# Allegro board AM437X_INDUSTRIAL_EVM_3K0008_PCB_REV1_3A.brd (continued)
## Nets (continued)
Pads without a net: J1 18; J3 9; J4 2; J5 14 16; J6 7; J7 6; J9 7; J18 4; NOREF 1; NOREF#4 1; NOREF#5 1; NOREF#6 1; NOREF#7 1; NOREF#8 1; NOREF#10 1; NOREF#11 1; NOREF#15 1; NOREF#16 1; NOREF#17 1; NOREF#18 1; NOREF#20 1; NOREF#21 1; NOREF#22 1; NOREF#24 1; NOREF#25 1; NOREF#26 1; NOREF#27 1; NOREF#28 1; NOREF#29 1; NOREF#30 1; R143 1; U4 4 6 8 10 12 16 17 19 21 27; U7 22; U8 1; U11 A5 A6 A7 AA7 AA9 AA10 AA19 AB6 AB7 AB9 AB10 AB19 AC5 AC6 AC7 AC9 AC10 AC12 AC24 AD1 AD2 AD7 AD10 AD11 AD22 AE7 AE8 AE9 AE10 AE11 AE12 B5 B6 B7 B8 C8 F24 F25 G21 G24 H19 M4 N6 T2 T25 U2 U22 U23 U24 U25 V24 V25 W10 W22 W24 W25 Y6 Y7 Y10; U12 22; U13 22 24 27 29 33 34 40 41 43 44 45 46 48 52 53 54 55 57 58; U20 J1 J9 L1 L9 M7; U21 J1 J9 L1 L9 M7; U23 21; U26 11 13 19 20; U27 4 9; U28 1; U33 2 4; U36 1; U37 45; U42 1; U46 4 5 6 11 12 13 14; U47 2; U48 1; U51 1; U54 1; U58 7 8 9 10; U59 2 5; Y1 2 4; Y3 2 3

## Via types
v1: diameter 0.457, hole 0.254, TOP to BOTTOM, 1263 vias
v2: diameter 0.508, hole 0.254, TOP to BOTTOM, 19 vias
v3: diameter 0.61, hole 0.305, TOP to BOTTOM, 1023 vias
v4: diameter 1.016, hole 0.508, TOP to BOTTOM, 123 vias

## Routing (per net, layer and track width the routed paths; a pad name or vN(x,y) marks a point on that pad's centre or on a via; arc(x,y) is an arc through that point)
AGND: length 2
  TOP w0.203: J5.1 125.2,105.56 125.41,105.78 125.41,106.11
  TOP w0.381: C15.2 125.41,106.11
AGNDFRAME_PRUETH0: length 9.3
  L5_PWR w0.508: J6.SHLD1 10.96,100.03 ; J6.SHLD1 8.96,100.03 ; J6.SHLD1 10.96,98.02 ; J6.SHLD2 10.96,82.27 ; J6.SHLD2 8.96,82.27 ; J6.SHLD2 10.96,84.28
  BOTTOM w0.508: C137.2 10.54,102.11 v3(10.53,102.1)
AGNDFRAME_PRUETH1: length 9.4
  L5_PWR w0.508: J9.SHLD1 10.96,74.02 ; J9.SHLD1 10.96,76.03 ; J9.SHLD1 8.96,76.03 ; 8.96,58.27 J9.SHLD2 ; J9.SHLD2 10.96,58.27 ; J9.SHLD2 10.96,60.28
  BOTTOM w0.508: C188.2 v3(10.41,77.98)
DGND: length 668.8
  TOP w0.13: U20.E2 v1(70.87,36.82)
  TOP w0.203: U11.A1 72.22,59.35 v1(71.82,59.75) ; U20.E8 75.64,36.8 v1(74.76,36.8) ; U21.G8 94.73,35.65 95.12,36.04 95.12,36.77 v1(95.16,36.81) ; J5.5 123.6,105.51 v3(123,106.11) 122.8,105.91 J5.7
  TOP w0.254: U13.13 121.75,63.21 v3(121.73,63.2) ; U20.E1 69.98,37.22 69.95,37.18 69.56,37.18 v1(69.47,37.09) ; v3(124.33,58.94) 124.06,59.21 U13.5 ; v1(69.55,38.04) 69.79,38.04 69.82,38.02 U20.D1 ; 92.33,17.27 92.58,17.02 92.58,16.97 92.89,16.66 93.19,16.66 93.35,16.5 U25.4 ; v1(96.7,31.88) 96.43,31.62 U21.M9 ; v1(87.99,58.94) 88.29,59.23 U11.AE1 ; U21.P1 88.95,30.02 v1(88.53,29.59) ; U21.E8 v1(95.13,37.62) ; U21.B9 95.65,39.73 v1(96.08,39.73) ; U13.10 122.06,61.71 v3(121.54,62.23) ; U20.G8 75.75,35.31 75.75,35.23 v1(75.74,35.22) ; U20.M1 69.98,31.62 69.85,31.74 v1(69.83,31.74) ; U21.D8 v1(94.33,37.62) ; v1(69.96,35.53) 70.04,35.62 U20.G1 ; U21.B3 v1(91.13,40.02) ; v1(77.36,31.69) 77.18,31.69 77.11,31.62 U20.M9 ; v1(86.24,73.25) 85.84,73.65 U11.AA23 ; U21.T1 89.13,28.13 88.75,27.75 v1(88.53,27.75) ; v1(95.12,34.37) 95.1,34.34 95.05,34.34 U21.J8 ; U11.W23 83.98,73.65 83.94,73.68 v1(83.89,73.68) ; v1(88.7,74.68) 88.43,74.95 U11.AE25 ; U20.T1 70.37,28.51 69.91,28.51 69.88,28.53 v1(69.72,28.53) ; v3(117.34,68.05) 117.2,68.05 116.98,67.82 U13.25 ; U20.F9 77.18,36.42 v1(77.35,36.25) ; U13.47 v3(112.72,57.71) ; v1(77.31,39.16) 77.3,39.16 76.86,39.6 U20.B9 ; U21.A9 95.62,40.32 v1(96.08,40.32) ; v3(60.58,13.97) 61.1,13.45 U26.6 ; v1(95.98,35.94) 95.98,35.91 95.69,35.62 U21.G9 ; U20.A9 76.86,40.84 76.94,40.92 v1(76.94,40.94) ; U20.B1 69.92,40.15 69.92,40.34 v1(69.9,40.36) ; U13.51 v3(114.48,53.72) ; v1(77.45,28.47) 77.4,28.42 U20.T9 ; U21.T9 95.53,27.97 v1(95.45,27.89) ; v1(72.1,74.56) 72.1,74.57 72.48,74.95 U11.A25 ; U13.1 v3(124.21,57.21) ; U21.B1 88.97,39.78 88.6,39.78 v1(88.57,39.8) ; U20.G9 77.1,35.62 77.11,35.61 77.32,35.61 77.78,35.15 77.78,35.09 78.08,34.8 v1(78.08,34.78) ; v1(71.7,34.42) 71.66,34.42 U20.J2 ; v1(96,36.61) 95.97,36.61 95.78,36.42 U21.F9 ; U13.11 v3(124.12,62.21) ; U26.12 62.84,9.57 v3(62.85,9.56) ; U20.P9 77.04,30.02 77.14,30.12 77.21,30.12 v1(77.32,30.22) ; U21.P9 95.63,30.12 v1(96.42,30.12) ; v1(88.62,37.25) 88.66,37.22 U21.E1 U21.E2 ; U21.J2 89.53,34.42 89.53,34.36 89.55,34.34 v1(89.54,34.34) ; v3(71.75,101.66) 71.34,102.08 U4.28 ; U20.B3 72.48,40.03 v1(72.48,40.02) ; U20.J8 75.64,33.6 v1(75.59,33.6) ; U13.35 110.53,63.71 v3(110.11,64.14) ; v1(88.62,35.59) 88.65,35.62 U21.G1 ; U21.M1 88.51,31.62 v1(88.27,31.37) ; U21.D1 v1(88.73,38.42) ; U20.P1 69.33,30.02 69.27,30.09 v1(69.23,30.09) ; U20.D8 v1(76.46,37.62)
  TOP w0.305: v3(42.93,36.07) 43.39,35.6 U23.20 ; U13.15 v3(124.28,64.21) ; U23.28 v3(38.19,35.81) ; v3(93.85,14.22) U25.8 ; U27.5 v3(47.37,3.17)
  TOP w0.381: v3(122.82,84.45) 122.81,84.47 U8.3 ; U6.11 v3(109.94,99.35) ; U6.2 v3(115.8,97.03) ; U9.10 v3(64.26,85.22) ; U6.13 v3(109.29,90.68) ; U6.12 v3(109.29,97.03)
  TOP w0.457: v3(28.83,35.69) 28.58,35.94 U18.2 ; U24.2 v3(61.09,28.07) ; U19.2 v3(61.09,37.34)
  TOP w0.508: C18.2 v3(93.6,102.56) ; C9.2 v3(83.91,110.3) ; v3(108.08,47.5) 109.09,47.5 109.73,46.86 U16.7 ; C33.2 v3(21.59,89.67) ; v3(84.96,101.85) 84.58,102.23 U5.7 ; v3(33.91,96.52) R44.1 R46.1 ; v3(49.02,23.88) R213.1 C100.2 ; v3(14.3,110.06) 14.22,110.13 R7.1 ; v3(39.5,98.3) R32.2 ; SW1.3 v3(134.62,59.4) SW1.4 ; C116.2 v3(59.69,2.79) ; R181.1 109.09,44.12 v3(109.04,44.17) 108.84,44.37 C78.2 ; C29.2 v3(86.74,91.44) ; C90.2 v3(30.23,31.5) ; C11.2 v3(62.61,110.1) ; 101.73,53.09 101.73,51.94 v3(102.49,51.94) ; SW2.2 v3(133.13,33.69) ; R191.1 v3(57.02,38.61) ; U22.2 50.29,30.51 v3(50.52,30.28) ; C73.2 v3(124.08,53.22) 124.2,53.34 R160.1 ; U5.10 v3(84.58,97.28) ; R94.1 v3(124.19,80.39) ; Q3.S 18.92,110.66 v3(18.92,112.39) ; R108.1 33.91,70.35 v3(34.68,70.35) ; C84.2 R185.1 v3(30.61,41.91) ; v3(76.73,97.03) C23.2 v3(75.56,95.63) ; R34.1 v3(73.53,96.01) ; v3(102.92,34.85) 102.62,34.54 R198.1 ; R212.1 v3(58.93,25.1) ; C85.2 v3(58.93,39.37) ; R33.1 v3(68.71,96.65) ; J7.12 v3(128.4,80.77) ; U16.5 v3(113.16,49.4) ; U5.9 v3(83.31,97.28) ; C6.2 v3(76.29,110.3) ; C10.2 v3(88.56,110.3) ; C91.2 v3(53.34,32.26) ; v3(102.51,58.72) 101.9,58.72 101.73,58.55 ; v3(89.43,12.42) 89.59,12.57 C112.2 ; C3.2 v3(68.67,110.3) ; v3(98.12,19.3) 97.52,19.3 C105.2 97.03,18.8 97.54,18.29 v3(98.12,18.29) ; C34.2 v1(61.65,86.87) ; v3(34.68,92.17) 34.65,92.2 R55.1 ; v3(97.92,16.89) 97.92,16 C109.2 ; C72.2 v3(13.47,54.23) ; v3(67.08,41.16) C80.2 v3(64.64,41.16) ; C24.2 v3(74.55,94.36) ; C19.2 v3(94.74,102.56) ; C61.2 v3(127.26,62.81) ; v3(36.83,93.98) C26.2 ; R202.1 v3(64.01,30.48) ; 101.73,54.74 v3(102.49,54.74) ; R192.1 v3(25.27,39.12) ; R175.1 v3(34.42,51.55) ; C30.2 v3(89.28,91.44) ; v3(102.87,11.68) C113.2 v3(101.58,10.43) ; R166.1 v3(18.15,51.82) ; v3(60.71,4.19) C115.2 59.65,5.12 v3(59.44,5.33) ; C46.2 v3(112.39,77.36) ; C41.2 v3(118.11,84.89) ; C68.2 v3(104.77,58.17) ; v3(36.96,98.81) C22.2 36.59,97.65 v3(35.69,98.55) ; C87.2 v3(47.62,35.69) ; C114.2 v3(64.01,7.62) ; v3(62.36,30.35) 61.98,30.73 C92.2 ; R81.1 v3(92.71,84.84) ; R55.1 R51.1 ; R55.1 R57.1 ; C16.2 80.77,106.93 81.14,107.3 v3(81.15,107.3) ; 31.12,85.72 30.35,85.72 v3(29.69,85.06) ; U14.7 v3(22.1,54.34) ; v3(48.39,98.17) 48.39,99.08 C21.2 48.01,99.44 47.62,99.82 v3(47.62,100.71) ; v3(94.61,13.72) 94.74,13.59 C111.2 ; C75.2 v3(45.47,53.84) ; U5.16 v3(92.2,97.41) ; v3(122.43,113.59) 123.05,113.59 Q1.S ; J7.20 v3(128.4,85.85) ; C20.2 v3(117.22,101.09) ; v3(110.24,40) 110.24,40.64 C82.2 ; U15.7 v3(44.28,53.09) ; v3(25.91,112.39) 25.91,110.71 Q5.S ; C14.2 v3(121.09,107.88) ; R9.1 6.65,110.87 v3(6.39,111.14) ; C104.2 v3(89.94,18.8) ; Q4.S 22.48,110.66 v3(22.48,112.39) ; R122.1 33.91,69.21 v3(34.68,69.21) ; C108.2 v3(89.4,15.75) ; v3(26.42,39.12) C86.2 ; v3(55.55,91.69) 55.17,91.31 C28.2 v3(54.34,90.04) ; C107.2 v3(96.53,17.27) ; R112.1 v3(112.4,70.87) ; SW2.1 v3(135.11,33.69) ; C64.2 v3(28.56,60.45) ; R169.1 v3(116.08,50.94) ; C76.2 111.64,51.82 v3(111.63,51.82) ; C44.2 v3(124.33,81.53) ; R19.2 v3(64.52,106.55) ; R18.1 v3(49.92,106.81) ; C101.2 v3(61.98,21.08) ; C8.2 v3(81.37,110.3) ; v3(121.28,117.47) 121.79,117.47 R1.1 ; R130.1 R127.1 33.91,68.07 v3(34.68,68.07) ; R566.2 70.23,82.75 69.55,82.07 v3(69.49,82.07) ; C93.2 v3(59.69,29.34) ; v3(30.48,72.64) 31.67,72.64 C49.2 32.08,72.64 v3(33.27,72.64) ; v3(128.85,106.11) R17.1 v3(128.85,108.14) ; C110.2 v3(18.8,14.35) ; R182.1 v3(121.91,43.05) ; C25.2 v3(119.51,93.6) ; U3.7 v3(60.53,109.09) ; C4.2 v3(71.21,110.3) ; R93.2 v1(111.38,81.43) ; C103.2 v3(100.18,21.08) ; U10.7 v3(113.58,78.11) ; v3(35.54,80.26) C43.2 v3(35.54,82.73) ; C7.2 v3(78.83,110.3) ; C89.2 v3(48.51,36.07) ; Q2.S 127.83,114.55 v3(128.02,114.55) ; C17.2 50.04,105.66 v3(49.91,105.79) ; v3(82.68,102.49) 83.31,103.12 U5.8 ; v3(28.58,41.91) 28.58,41.15 C83.2 ; R53.1 v3(50.29,92.02) ; v3(51.05,94.61) 50.93,94.61 50.29,95.25 R45.1 ; C63.2 v3(39.5,61.09) ; R197.2 v3(50.42,36.07) ; J7.16 v3(128.4,83.31) ; J7.8 v3(128.4,78.23) ; R176.1 v3(46.48,49.66) ; v3(81.41,20.59) C102.2 v3(82.68,19.43) ; C62.2 v3(102.49,61.82) ; C60.2 103.76,65.41 v3(104.01,65.41) ; v3(11,110.01) 11.3,110.31 R11.1 ; C13.2 v3(118.81,107.88) ; C5.2 v3(73.75,110.3) ; C77.2 v3(34.42,48.91) ; C58.2 v3(21.59,64.4) ; C65.2 v3(31.12,59.69) ; C79.2 v3(122.05,44.2) ; C69.2 v3(13.47,56.52) ; U17.7 v3(111.25,40.77) ; R156.1 v3(13.47,55.37) ; 27.81,85.72 v3(28.56,85.72)
  L2_GND w0.508: 136.61,71.08 TP9.1 ; TP9.1 136.61,72.69 ; TP9.1 138.22,72.69 ; TP9.1 138.22,71.08 ; 104.57,117.49 J1.30 ; J1.30 104.57,116.06 ; J1.30 106,117.49 ; J1.30 106,116.06 ; 28.75,118.3 J4.12 ; J4.12 30.19,118.3 ; J4.12 30.19,116.87 ; J4.12 28.75,116.87 ; 135.19,24.72 J13.2 ; J13.2 136.81,24.72 ; J13.2 135.19,26.33 ; J13.2 136.81,26.33 ; J1.29 106,114.95 ; J1.29 104.57,113.52 ; J1.29 104.57,114.95 ; J1.29 106,113.52 ; 106.63,4.56 J16.22 ; J16.22 108.06,4.56 ; J16.22 106.63,3.13 ; J16.22 108.06,3.13 ; J1.17 90.76,113.52 ; J1.17 89.33,113.52 ; J1.17 89.33,114.95 ; J1.17 90.76,114.95 ; 63.08,3.73 TP16.1 ; TP16.1 63.08,2.12 ; TP16.1 64.69,3.73 ; TP16.1 64.69,2.12 ; J8.2 26.33,75.61 ; J8.2 24.72,75.61 ; J8.2 26.33,74 ; J8.2 24.72,74 ; 127.04,26.18 J12.2 ; J12.2 130,26.18 ; J12.2 127.04,29.14 ; J12.2 130,29.14 ; 68.63,6.56 J16.59 ; J16.59 70.06,5.13 ; J16.59 68.63,5.13 ; 14.48,1.91 J15.6 ; J15.6 16,1.91 ; J15.6 14.48,3.43 ; J15.6 16,3.43 ; 88.63,3.13 J16.40 ; J16.40 90.06,3.13 ; J16.40 90.06,4.56 ; J16.40 88.63,4.56 ; J3.10 15.54,108.51 ; J3.10 13.92,108.51 ; J3.10 13.92,106.88 ; J6.8 16.51,87.42 ; J6.8 16.51,85.99 ; J6.8 15.08,87.42 ; J6.8 15.08,85.99 ; 68.63,3.13 J16.60 ; J16.60 68.63,4.56 ; J16.60 70.06,4.56 ; J16.60 70.06,3.13 ; 42.2,116.27 J4.13 ; J4.13 43.64,114.84 ; J4.13 43.64,116.27 ; TP11.1 3.47,51.9 ; TP11.1 1.86,51.9 ; TP11.1 1.86,53.51 ; TP11.1 3.47,53.51 ; 130.29,21.38 J12.3 ; J12.3 133.25,24.34 ; J12.3 133.25,21.38 ; J12.3 130.29,24.34 ; TP1.1 58.34,118.15 ; TP1.1 56.73,116.54 ; TP1.1 56.73,118.15 ; TP1.1 58.34,116.54 ; 88.63,6.56 J16.39 ; J16.39 88.63,5.13 ; J16.39 90.06,5.13 ; J16.39 90.06,6.56 ; J4.1 42.63,104.84 ; J4.1 41.19,104.84 ; J4.1 41.19,103.41 ; J4.1 42.63,103.41 ; J9.8 16.51,61.99 ; J9.8 16.51,63.42 ; J9.8 15.08,61.99 ; J9.8 15.08,63.42
  L3_SIG1 w0.508: 15.08,85.99 J6.8 15.08,87.42
  L4_SIG2 w0.508: J6.8 16.51,85.99 ; J6.8 16.51,87.42 ; J6.8 15.08,85.99
  BOTTOM w0.203: U40.C1 v3(115.45,85.85) ; J19.13 55.33,1.78 ; v3(64.93,108.08) 65.31,107.7 U29.C1 ; U52.C1 v3(42.41,45.72) ; U49.5 131.1,49.57 v1(130.81,49.28) ; U41.5 128.43,83.35 v3(128.4,83.31) ; U53.C1 v3(113.16,48.13) ; J19.14 41.07,1.65
  BOTTOM w0.254: 100.46,92.58 100.81,92.94 U35.C4 ; U35.C1 104.62,92.94 104.9,93.22 v1(104.9,93.47) ; 102.57,94.71 102.33,94.47 102.33,94.07 U35.A2 ; U35.C3 U35.C4 ; U35.C4 U35.D4 ; v3(47.62,96.01) 47.07,95.46 U37.13 ; U37.29 43.93,90.44 v3(43.18,91.19)
  BOTTOM w0.305: U31.2 v3(134.37,102.23) ; U59.4 v3(54.6,19.17) ; U47.4 131.45,64 v3(130.94,64.52) ; U38.8 131.07,90.69 v3(131.44,91.06) ; U38.3 v3(134.33,90.93) ; U45.8 v3(124.47,68.07) ; U45.9 v3(124.47,71)
  BOTTOM w0.381: U38.9 131.07,94.1 v3(131.44,93.73) ; J19.6 v3(40.37,3.36) ; U50.3 124.47,50.68 v3(124.84,51.05) ; C301.2 v1(95.12,34.37) ; C193.2 85.58,73.91 v1(86.24,73.25) ; v1(88.57,39.8) 88.24,39.8 88.06,39.62 C283.2 ; U42.3 31,82.68 v3(31.31,82.99) ; U34.2 125.98,92.08 v3(125.73,91.82) ; J18.5 135.07,61.69 v3(134.54,61.17) ; v1(69.83,31.74) 69.67,31.74 69.54,31.88 C315.2 ; v3(14.1,74.74) U44.3 ; U33.10 v3(22.1,99.68) ; C294.2 89.32,37.25 v1(88.62,37.25) ; v1(69.47,37.09) 69.21,36.83 C297.2 ; C195.2 83.54,73.68 v1(83.89,73.68) ; v1(69.72,28.53) 69.71,28.53 69.5,28.32 C324.2 ; U58.11 37.34,28.82 v3(36.96,29.21) ; U36.3 v3(76.2,92.31) ; v3(135.64,93.6) 134.98,94.26 U38.15 ; U48.3 108.09,57.67 v3(108.58,58.17) ; U58.13 v3(37.99,20.31) ; U51.3 127.65,50.84 v3(127.54,50.95) ; C290.2 94.23,37.71 v1(94.33,37.62) ; U43.3 21.29,79.12 v3(20.57,79.12) ; U58.12 v3(37.99,26.42) ; v1(69.55,38.04) 69.48,38.04 69.41,37.97 C289.2 ; C285.2 77.01,39.45 77.3,39.16 v1(77.31,39.16) ; v3(135.76,45.97) 135.14,45.35 U54.3 ; v1(71.7,34.42) 71.66,34.46 71.66,35.08 C302.2 ; C187.2 v3(28.7,77.48) ; C328.2 89.22,27.75 v1(88.53,27.75) ; v3(125.73,96.65) 125.98,96.39 U34.5 ; C197.2 78.96,73.32 78.94,73.33 78.94,75.61 78.4,76.16 v3(78.4,76.2) ; U38.14 v3(134.33,93.89) ; U39.10 v3(55.75,92.71) ; v1(96.42,30.12) 96.69,29.84 C318.2 ; U33.5 v3(25.65,99.68)
  BOTTOM w0.508: R549.1 97.92,15.75 v3(97.92,16.89) ; C227.2 v3(117.79,64.27) ; v1(95.98,35.94) C296.2 ; v3(111.55,54.09) 111.57,54.11 C258.2 v3(110.61,55.07) ; C314.2 88.77,31.88 v1(88.27,31.37) 88.11,31.22 88.01,31.22 87.91,31.12 C316.2 ; Q8.S v3(6.39,111.14) ; R335.1 R334.1 R333.1 R332.1 R331.1 R330.1 R329.1 R328.1 v3(67.82,96.33) ; v3(57.75,9.65) R557.1 R556.1 ; v3(121.73,63.2) 121.78,63.25 R460.2 ; U32.3 v3(84.58,97.28) ; C186.2 128.52,78.36 v3(128.4,78.23) ; C190.2 v3(133.73,76.96) ; J19.12 v3(41.26,9.47) ; C149.2 v3(51.05,94.61) ; C142.2 v3(46.35,99.69) ; U32.2 v3(85.85,97.28) ; C295.2 74.88,36.88 74.79,36.8 v1(74.76,36.8) ; C139.2 v3(29.59,101.6) ; v1(76.46,37.62) 76.18,37.62 75.69,38.1 C288.2 ; v3(25.53,59.56) 25.15,59.94 R464.1 ; U46.10 46.32,68.45 v3(45.71,67.85) ; C344.2 v3(63.37,18.8) ; R315.1 R314.1 v3(67.69,100.97) ; R554.1 v3(26.38,12.42) ; v3(84.45,16.78) C342.2 v3(87,16.78) ; C170.2 133.48,86.23 v3(133.6,86.36) ; U56.3 v3(53.09,40.17) ; v1(96.7,31.88) 96.54,31.88 96.42,32 C312.2 ; v3(129.97,101.03) C136.2 v3(129.97,103.57) ; v3(56.93,13.97) 57.06,13.84 R550.1 57.78,12.86 R551.1 ; C226.2 v3(133.92,67.06) ; U55.5 v3(22.73,47.62) ; v3(25.91,112.39) 25.91,111.89 R274.1 ; C242.2 65.79,62.36 v3(65.91,62.23) ; C235.2 v3(128.91,62.86) ; R319.1 R318.1 v3(62.1,100.97) ; C250.1 v3(120.02,57.03) ; R452.1 34.78,65.63 v3(34.8,65.65) ; v3(61.85,39.5) C286.2 ; U57.5 v3(3.37,25.65) ; C147.2 21.54,96.27 22.1,95.71 22.12,95.71 v3(22.15,95.68) ; C177.2 76.07,82.43 v3(76.33,82.17) ; C208.2 v3(22.23,68.96) ; C225.2 v3(129.92,65.66) ; C274.1 v3(123.95,44.32) ; R301.1 v3(113.66,106.55) ; v3(22.23,85.29) C167.2 v3(21.03,86.5) ; C222.2 v3(21.46,66.04) ; v1(78.08,34.78) 78.16,34.78 78.95,35.56 79.12,35.56 ; R276.1 22.48,111.76 v3(22.48,112.39) ; C215.2 21.97,67.95 v3(22.23,68.2) ; J19.11 v3(55.76,10.96) ; v1(75.74,35.22) 76.07,35.55 C299.2 ; C178.2 v3(22.11,83.82) ; Q7.S v3(11,110.01) ; v1(69.96,35.53) 69.72,35.3 C304.2 ; C130.1 v3(18.92,105.03) ; C346.2 v3(61.09,18.8) ; 29.46,22.73 v3(28.7,22.73) ; v3(39.62,81.67) R398.1 R397.1 ; C137.1 v3(12.32,103) ; v3(21.85,30.1) R513.2 v3(20.84,29.09) ; C345.2 v3(62.23,18.8) ; C245.1 v3(117.61,62.83) ; v3(104.39,54.99) 104.65,55.24 R476.1 ; C334.2 60.83,24 v3(60.45,23.62) ; v3(22.1,60.13) C244.2 v3(20.9,61.23) ; C309.2 R509.1 v3(62.99,31.5) ; C143.2 v3(44.83,99.69) ; v3(52.96,33.15) 52.45,32.64 C91.2 ; v3(133.73,84.33) C174.2 ; v3(62.84,68.84) 62.97,68.71 C212.2 ; C335.2 v3(104.76,25.65) ; C335.2 v3(104.76,23.11) ; C335.2 v3(105.89,24.38) ; v1(96.08,40.32) 96.4,40.64 C282.2 ; C255.2 129.41,57.66 v3(129.92,58.17) ; C127.2 v3(88.9,105.92) ; v3(26.54,90.26) 26.32,90.04 C163.2 C164.2 ; v3(125.98,90.68) C156.2 ; C262.2 v3(138.4,53.59) ; v3(98.6,37.67) 98.3,37.97 C291.2 ; v3(47.88,28.83) 48.39,29.34 C325.2 ; v3(98.55,56.9) C257.2 97.39,57.49 97.93,58.03 v3(98.55,58.03) ; v1(84.48,32.49) 84.48,32.48 84.84,32.13 C311.2 ; v1(80.14,84.84) 79.88,84.58 C176.2 ; C263.2 v3(106.81,51.82) ; v3(64.9,100.97) R316.1 R317.1 ; C191.2 63.4,75.79 v3(62.67,75.79) ; C330.2 v3(71.45,27.17) ; v3(114.95,64.41) C228.2 v3(116.14,63.3) ; 133.73,69.47 133.73,68.32 v3(133.64,68.23) ; 133.73,69.47 v3(132.08,69.47) ; 133.73,69.47 v3(133.73,70.87) ; C326.2 45.85,29.72 v3(45.21,30.35) ; v1(91.13,40.02) 91.13,40.71 C278.2 ; C293.2 57.15,36.7 v3(57.02,36.58) ; C169.2 v3(128.4,85.85) ; C251.1 v3(117.65,57.19) ; C183.2 56.19,79.38 55.83,79.73 v3(55.83,80.14) ; C350.2 v3(30.91,13.1) ; U32.4 v3(83.31,97.28) ; C129.1 v3(23.49,105.03) ; v3(122.18,103.01) 122.36,103.18 R304.1 ; v3(59.31,100.97) R320.1 R321.1 ; C125.2 v3(112.14,108.08) ; v1(95.45,27.89) 95.5,27.84 C329.2 ; J19.9 v3(44.05,14.75) ; 68.58,40.26 68.68,40.36 v1(69.9,40.36) ; v1(81.76,55.15) 81.66,55.25 R474.2 ; v3(39.62,30.35) 39.88,30.1 C327.2 ; C162.2 v3(50.29,89.66) ; v3(72.77,95.12) 72.39,94.74 R341.1 R342.1 ; v3(94.61,14.73) 95.12,15.24 C341.2 95.14,16.78 95.63,17.27 v3(96.53,17.27) ; v3(22.23,93.47) 21.97,93.22 C153.2 ; v3(37.34,78.74) 37.48,78.88 C182.2 v3(36.32,80.26) ; C122.1 v3(46.99,114.03) ; v3(110.11,64.14) 110.49,63.75 C239.2 ; v3(24.26,84.84) 24.26,85.72 ; C180.2 v3(68.21,81.53) C179.2 ; C121.1 v3(25.78,115.32) ; C287.2 v3(130.94,39.61) ; C338.2 97.54,19.88 v3(98.12,19.3) ; 18.8,6.73 v3(18.8,5.97) ; C347.2 v3(19.56,11.81) ; v3(121.28,115.95) C117.2 v3(122.44,114.68) ; C307.2 v3(66.93,34.29) ; U30.2 v3(109.6,104.58) ; U28.2 127.25,114.3 127.51,114.55 v3(128.02,114.55) ; C151.2 v3(128.65,94.36) ; v3(132.33,74.55) 132.21,74.42 R433.1 ; C145.2 v3(136.65,97.92) ; C348.2 v3(38.73,13.39) ; C320.2 v3(3.05,28.32) ; R541.2 v3(28.45,21.97) ; v3(107.95,67.95) C214.2 v3(106.79,66.75) ; J19.15 v3(50.8,15.25) ; C349.2 v3(23.68,12.42) ; v3(51.87,39.77) C280.2 50.67,38.67 v3(50.68,38.66) ; C249.2 111.88,58.55 v3(112.72,57.71) ; v1(70.87,36.82) 70.84,36.82 70.58,37.08 C292.2 ; R553.1 v3(37.59,13.39) ; C185.2 v3(16.89,79.12) ; v3(63.5,23.11) C333.2 R539.1 ; R429.1 v3(132.33,75.69) ; C275.1 v3(126.23,44.07) ; C264.2 v3(134.75,51.94) ; C126.2 v3(134.68,107.88) ; C351.2 v3(19.56,9.27) ; v3(36.83,93.98) C26.2 ; U32.1 87.12,100.3 v3(86.69,100.74) ; C277.2 76.96,40.97 v1(76.94,40.94) ; C261.2 129.92,54.23 v3(130.05,54.36) ; C267.2 v3(27.56,47.62) ; v3(53.09,30.28) 53.09,30.23 52.7,29.84 C321.2 ; v3(124.84,113.59) C123.2 v3(122.43,113.59) ; C157.2 v3(106.05,89.55) ; v3(32.26,31.24) R515.2 ; R340.1 v3(67.88,94.8) ; C281.2 v3(134.75,39.88) ; v3(18.92,112.39) 18.92,111.76 R278.1 ; v3(30.35,30.48) C319.2 ; C259.2 v3(116.46,53.85) ; C173.2 v3(69.34,85.22) ; C265.2 v3(130.56,51.18) ; C146.2 v3(127.64,97.66) ; C150.2 v3(21.46,95) ; C246.1 v3(120.02,62.74) ; v1(77.45,28.47) 77.52,28.47 77.66,28.32 C323.2 ; C343.2 v3(64.52,18.8) ; v3(96.65,103.38) C128.2 v3(97.92,104.66) ; v1(72.1,74.56) 72.12,74.56 72.52,74.17 C192.2 ; C260.1 114.05,54.15 v3(114.48,53.72) ; R372.1 v3(39.62,84.33) ; C141.2 v3(29.59,97.92) ; 55.33,1.78 v3(54.61,1.78) ; C188.1 v3(12.32,78.74) ; C196.2 v3(131.19,73.15) ; v3(50.52,30.28) 50.29,30.05 R518.1 ; J19.16 v3(46.97,15.25) ; C132.2 v3(115.19,106.43) ; C237.2 C232.2 25.75,64.86 v3(26.42,64.86) ; C166.2 v3(136.65,88.52) ; C194.2 v3(21.46,73.79) ; v3(28.96,12.32) R555.1 ; Q6.S v3(14.3,110.06) ; C155.2 v3(21.46,91.31) ; R369.1 v3(43.05,84.33) ; R366.1 v3(46.48,84.33) ; C140.2 v3(132.65,98.17) ; C154.2 v3(77.72,91.44) ; R394.1 v3(44.2,81.67) ; 41.07,1.65 v3(40.13,1.65) ; C290.2 C284.2
  vias: v1(38.72,87.27) v1(44.6,72.24) v1(47.75,88.65) v1(50.16,59.05) v1(55.5,60.07) v1(55.73,87.05) v1(56.26,71.12) v1(59.21,73.23) v1(62.76,48.11) v1(62.76,47.22) v1(62.76,46.33) v1(62.76,45.44) v1(62.76,44.55) v1(62.76,43.66) v1(62.76,42.77) v1(62.76,41.88) v1(64.59,48.66) v1(66.15,44.47) v1(66.8,60.2) v1(66.96,47.63) v1(67,46.2) v1(67.34,40.06) v1(67.36,37.85) v1(67.36,36.96) v1(67.36,36.07) v1(67.36,35.18) v1(67.53,29.76) v1(68.1,41.88) v1(68.27,29.73) v1(68.25,28.88) v1(68.61,25.82) v1(69.5,24.93) v1(70.23,24.13) v1(70.76,51.84) v1(70.99,23.37) v1(71.59,52.38) v1(71.96,22.4) v1(72.9,46.86) v1(73.15,33.73) v1(73.53,34.42) v1(73.53,21.59) v1(73.53,20.7) v1(73.74,50.7) v1(74.42,20.57) v1(74.82,43.91) v1(75.18,23.88) v1(75.34,42.15) v1(75.45,45.64) v1(75.44,20.57) v1(75.9,45.21) v1(75.95,52.45) v1(76.07,23.88) v1(76.4,52.99) v1(76.34,45.64) v1(76.51,42.95) v1(76.78,70.66) v1(77.13,42.37) v1(77.46,54.22) v1(77.83,46.77) v1(77.98,21.36) v1(78.14,43.1) v1(78.48,49.75) v1(78.56,50.59) v1(78.71,36.23) v1(78.88,69.35) v1(78.86,65.02) v1(79.35,68.93) v1(79.5,20.57) v1(79.63,23.42) v1(80.21,44.65) v1(80.14,20.68) v1(80.52,24.05) v1(81.04,52.62) v1(81.04,51.73) v1(81.41,24.05) v1(81.62,66.98) v1(81.62,65.37) v1(81.76,54.46) v1(82.1,68.85) v1(82.17,25.83) v1(82.62,69.29) v1(82.66,66.93) v1(83.2,50.23) v1(83.27,49.34) v1(83.54,70.89) v1(83.96,71.38) v1(83.95,23.62) v1(84.2,66.01) v1(84.2,20.57) v1(84.5,46.51) v1(84.58,64.16) v1(84.68,55.4) v1(84.64,50.14) v1(84.84,23.62) v1(84.94,63.72) v1(85.35,64.18) v1(85.5,62.81) v1(85.47,20.57) v1(85.72,44.17) v1(85.72,23.62) v1(86.61,23.62) v1(86.74,20.57) v1(87.2,29.08) v1(87.5,23.62) v1(88.39,23.62) v1(88.9,20.57) v1(89.28,23.62) v1(89.64,26.62) v1(90.04,20.57) v1(91.31,20.57) v1(92.19,54.93) v1(92.43,27.46) v1(92.43,26.57) v1(92.56,34.87) v1(92.61,31.65) v1(92.58,20.57) v1(92.63,32.82) v1(93.7,26.54) v1(95.5,22.35) v1(95.81,49.07) v1(96.14,48.11) v1(96.29,52.41) v1(96.49,48.82) v1(96.49,47.42) v1(96.77,21.08) v1(97.07,42.8) v1(97.16,23.37) v1(97.16,22.35) v1(97.56,46.86) v1(98.04,23.37) v1(98.04,22.35) v1(98.17,26.29) v1(98.4,35.15) v1(98.4,34.26) v1(98.4,32.99) v1(98.88,30.71) v1(99.09,37.01) v1(99.07,23.54) v1(99.87,29.95) v1(100.2,19.3) v1(102.11,43.05) v1(102.11,42.29) v1(102.36,43.81) v1(102.74,43.05) v1(102.74,42.29) v1(102.87,38.1) v1(102.87,37.34) v1(102.87,36.58) v1(102.87,35.69) v3(7.87,8.13) v3(9.4,8.13) v3(12.95,18.29) v3(12.95,17.02) v3(13.59,22.23) v3(13.59,20.95) v3(14.22,18.29) v3(14.22,17.02) v3(23.49,22.35) v3(23.49,21.08) v3(23.49,19.81) v3(23.62,17.14) v3(23.62,15.88) v3(24.77,22.35) v3(24.77,21.08) v3(24.89,17.14) v3(24.89,15.88) v3(26.16,17.14) v3(26.16,15.88) v3(26.42,67.15) v3(26.42,66.01) v3(26.54,92.3) v3(26.54,91.28) v3(27.43,17.14) v3(27.56,92.3) v3(27.56,91.28) v3(27.56,90.26) v3(27.56,67.15) v3(27.56,66.01) v3(27.56,64.86) v3(28.58,92.3) v3(28.58,91.28) v3(28.58,90.26) v3(28.7,67.15) v3(28.7,66.01) v3(28.7,64.86) v3(28.7,49.02) v3(29.21,72.64) v3(29.97,50.29) v3(29.97,49.02) v3(32,61.21) v3(33.78,48.01) v3(33.78,46.74) v3(33.78,45.47) v3(34.67,99.31) v3(35,61.7) v3(35.04,48.01) v3(35.04,46.74) v3(35.05,45.47) v3(38.23,33.15) v3(38.23,31.75) v3(38.23,30.35) v3(39.62,76.15) v3(39.62,74.88) v3(39.62,33.15) v3(39.62,31.75) v3(40.89,76.15) v3(40.89,74.88) v3(41.02,33.15) v3(41.02,31.75) v3(41.02,30.35) v3(41.66,94.23) v3(41.66,92.71) v3(41.66,91.19) v3(41.91,17.02) v3(42.42,33.15) v3(42.42,31.75) v3(42.42,30.35) v3(42.67,44.58) v3(42.67,43.31) v3(42.67,42.04) v3(43.18,94.23) v3(43.18,92.71) v3(43.18,17.02) v3(43.81,33.15) v3(43.81,31.75) v3(43.81,30.35) v3(43.94,43.31) v3(43.94,42.04) v3(44.58,18.29) v3(44.58,17.02) v3(44.7,94.23) v3(44.7,92.71) v3(44.7,91.19) v3(45.21,33.15) v3(45.21,31.75) v3(45.34,58.42) v3(45.34,55.88) v3(46.61,58.42) v3(46.61,57.15) v3(46.61,55.88) v3(46.61,33.15) v3(46.61,31.75) v3(46.61,30.35) v3(49.75,88.79) v3(49.76,72.19) v3(49.76,70.99) v3(49.78,69.98) v3(49.76,66.17) v3(49.76,64.9) v3(49.76,63.63) v3(49.76,56.64) v3(49.76,55.37) v3(49.89,78.87) v3(49.89,77.6) v3(49.89,76.33) v3(50.55,88.02) v3(51.05,69.98) v3(51.05,63.63) v3(51.18,76.33) v3(52.02,86.73) v3(57.78,68.71) v3(58.29,97.92) v3(59.82,97.92) v3(61.19,77.17) v3(61.44,97.94) v3(61.59,115.7) v3(61.59,114.43) v3(61.59,111.89) v3(62.58,13.21) v3(62.58,11.68) v3(62.86,115.7) v3(62.86,114.43) v3(62.86,113.16) v3(62.86,111.89) v3(63.42,29.9) v3(63.34,12.45) v3(64.1,13.21) v3(64.1,11.68) v3(64.14,115.7) v3(64.14,114.43) v3(64.26,97.92) v3(65.28,115.7) v3(65.53,97.92) v3(71.75,100.39) v3(73.02,101.66) v3(73.02,100.39) v3(74.3,102.93) v3(74.3,101.66) v3(74.3,100.39) v3(75.56,102.93) v3(75.56,101.66) v3(75.56,100.39) v3(76.83,102.93) v3(76.83,101.66) v3(76.83,100.39) v3(78.11,102.93) v3(78.11,101.66) v3(78.11,100.39) v3(78.63,92.36) v3(78.92,93.5) v3(79.38,102.93) v3(79.38,101.66) v3(79.38,100.39) v3(80.19,93.47) v3(81.46,92.18) v3(87.88,96.27) v3(87.88,95.38) v3(88.39,87.12) v3(89.03,96.27) v3(89.03,95.38) v3(89.15,18.8) v3(89.66,85.85) v3(89.92,18.03) v3(93.09,14.73) v3(93.09,13.72) v3(105.92,106.43) v3(105.92,105.16) v3(107.19,106.43) v3(108.97,37.97) v3(108.97,36.7) v3(108.97,35.43) v3(110.24,37.97) v3(110.24,35.43) v3(111.38,75.31) v3(111.38,72.77) v3(111.63,50.55) v3(112.52,75.31) v3(112.52,72.77) v3(112.9,50.55) v3(113.92,89.15) v3(113.92,87.88) v3(115.19,89.15) v3(115.19,87.88) v3(115.19,86.74) v3(120.52,48.39) v3(120.53,47.12) v3(120.53,45.85) v3(121.79,47.12) v3(121.79,45.85) v3(122.81,85.72) v3(122.82,83.19) v3(124.08,85.72) v3(124.08,84.45) v3(124.08,83.19) v3(129.41,113.11) v3(130.68,113.11) v4(14.86,59.69) v4(14.86,57.91) v4(16.64,59.69) v4(30.73,54.86) v4(30.73,53.09) v4(32,51.69) v4(32,50.04) v4(33.27,51.69) v4(33.27,50.04) v4(48.13,111.51) v4(48.13,109.86) v4(48.13,108.08) v4(48.13,106.3) v4(63.25,103.89) v4(63.25,102.13) v4(65.02,105.66) v4(65.02,103.89) v4(65.02,102.11) v4(97.41,96.84) v4(97.66,98.49) v4(98.93,90.55) v4(99.06,96.84) v4(100.58,90.55) v4(100.58,88.9) v4(105.92,97.92) v4(105.92,96.27) v4(112.9,30.86) v4(113.84,14.73) v4(113.84,13.08) v4(113.84,11.43) v4(114.17,32.26) v4(114.17,30.86) v4(115.95,10.68) v4(117.98,32.64) v4(117.98,30.99) v4(119.25,10.68) v4(119.76,32.64) v4(119.76,30.99) v4(123.83,42.04) v4(125.48,40.39) v4(125.6,81.03) v4(127.13,40.39) v4(127.25,81.03) v4(127.25,79.38) v4(127.25,77.72)
GND_ETH1: length 8.5
  BOTTOM w0.508: J4.SHLD2 29.45,108.96 ; J4.SHLD2 27.44,108.96 ; J4.SHLD2 27.44,110.97 ; J4.SHLD1 44.95,108.96 ; J4.SHLD1 42.94,108.96 ; J4.SHLD1 44.95,110.97
GND_OSC0: length 4.7
  TOP w0.14: 73.2,75.36 73,75.16 73,74.64
  TOP w0.254: U11.B24 73,74.64 ; 73.2,75.36 74.17,76.33 74.17,77.34 73.41,78.11
  vias: v3(71.35,85.47) v3(71.75,90.8)
GND_OSC1: length 0.5
  TOP w0.254: v1(87.2,61.5) 87.4,61.3 U11.AD4
GNDA_ADC: length 507.5
  TOP w0.254: v1(86.99,67.98) U11.AC15 U11.AD15 U11.AE14 88.43,67.95 88.87,67.95
  TOP w0.508: 117.27,117.49 117.98,116.77 ; 117.98,116.77 118.7,116.06 ; 117.98,116.77 117.27,116.06 ; 117.98,116.77 118.7,117.49 ; J2.3 121.28,109.35 ; J2.3 119.76,109.35 ; J2.3 121.28,110.87 ; J2.3 119.76,110.87 ; C55.2 C54.2 C57.2 ; C57.2 C56.2 95.81,69.34 94.41,67.95 88.87,67.95 ; C57.2 v3(97.28,70.23) ; 117.27,114.95 117.98,114.23 ; 117.98,114.23 118.7,113.52 ; 117.98,114.23 118.7,114.95 ; 117.98,114.23 117.27,113.52 ; v3(111.51,77.04) 110.36,75.9 110.36,72.31 111.45,71.23 v3(111.45,68.66) v3(111.45,67.2)
  L3_SIG1 w0.381: 63.55,9.47 64.19,9.47 66,11.28 66,12.24 67.16,13.4 69.34,13.4 70.52,14.58 v3(76.29,14.58) 76.29,13.27 77.62,11.94 77.62,11.33 79.06,9.89 91.11,9.89 91.77,9.23 95.39,9.23 96.04,9.87 99.03,9.87 99.83,10.68 100.46,10.68 102.98,13.21 102.98,15.81 105.07,17.89 106.35,17.89 107.07,18.61 107.07,21.81 108.66,23.41 108.66,28.02 113.8,33.16 115.58,33.16 117.27,34.85 118.69,34.85 v3(119.35,35.51) 118.53,36.33 116.65,36.33 114.92,34.61 113.2,34.61 107.21,28.62 107.21,24.01 105.62,22.41 105.62,20.49 101.52,16.4 101.52,14.15 v3(101.09,13.72) ; 61.42,13.31 62.45,14.34 66.05,14.34 68.72,17.01 76.03,17.01 76.13,16.9 77.25,16.9 v3(77.93,16.23) 78.94,15.21 83.36,15.21 84.77,13.8 89.97,13.8 90.76,13.02 95.72,13.02 97,14.3 97,15.13 98.07,16.19 98.31,16.19 99.16,17.04 99.16,17.58 100.13,18.55 101.22,18.55 v3(101.81,19.15)
  L4_SIG2 w0.381: 96.82,38.02 96.82,37.16 97.77,36.21 97.77,32.79 98.15,32.41 98.15,27.35 99.69,25.81 99.69,22.52 98.82,21.65 98.82,17.01 100.58,15.24 100.58,14.22 v3(101.09,13.72) 101.81,14.44 v3(101.81,19.15) 101.81,26.6 101.89,26.68 102.73,27.52 102.73,32.04 101.71,33.06 101.71,33.51 101.71,38.46 100.36,39.81 100.36,48.88 98.7,50.53 98.7,51.91 97.04,53.57 97.04,54.06 96.53,54.57 96.26,54.57 95.02,55.81 95.02,58.85 91.99,61.89 91.99,62.72 89.84,64.87 89.84,68.58 88.51,69.91 87.53,69.91 ; 87.35,60.95 87.35,54.63 88.82,53.16 88.82,50.18 90.5,48.5 91.89,48.5 92.39,48 92.39,47.31 94.87,44.83 94.87,41.53 ; 109.67,69.26 110.27,68.66 v3(111.45,68.66) 112.85,68.66 113.12,68.39 114.71,68.39 118.81,64.29 118.81,59.45 120.72,57.54 120.72,56.74 119.79,55.81 119.79,45.33 119.82,45.3 119.82,43.57 118.99,42.74 118.99,35.88 v3(119.35,35.51) ; 117.48,39.6 117.48,45.29 118.34,46.15 118.34,57.86 117.36,58.85 117.36,61.09 115.44,63.01 115.44,63.91 115.64,64.12 115.64,65.41 114.11,66.94 111.71,66.94 v3(111.45,67.2) 110.05,67.2 109.68,67.2 107.88,69 105.45,69
  L4_SIG2 w0.508: v3(115.95,108.71) v3(115.14,107.9) 114.43,107.19 114.43,103.15 115.16,102.42 115.16,100.39 114.15,99.38 114.15,97.46 115.14,96.47 115.14,94.63 116.59,93.18 v3(116.59,90.55) v3(116.59,89.53) 116.59,86.54 117.35,85.78 117.35,84.57 118.5,83.42 118.5,81.8 113.16,76.45 112.09,76.45 v3(111.51,77.04) 110.92,76.45 107.11,76.45 v3(106.43,75.77)
  BOTTOM w0.381: 87.98,68.17 87.17,68.17 v1(86.99,67.98) ; 57.47,24.37 57.47,21.17 59,19.63 68.05,19.63 70.17,17.51 73.29,17.51 76.23,14.58 v3(76.29,14.58) 81.81,14.58
  BOTTOM w0.508: 62.84,21.18 68.68,21.18 70.84,19.02 75.16,19.02 77.93,16.26 v3(77.93,16.23) ; v3(106.43,75.77) 105.54,75.77 104.7,74.93 104.7,74.38 103.9,73.58 99.97,73.58 97.28,70.89 v3(97.28,70.23) 95.25,68.2 R444.2 C217.2 87.98,68.17
GNDUSBJ:
  vias: v3(136.6,56.92) v3(138.1,56.9) v3(138.27,69.72) v3(138.27,68.71)
V1_5D: length 163.2
  TOP w0.254: v1(81.31,62.55) 81.73,62.55 U11.R6 U11.R7 U11.T7 ; v1(81.33,63.41) 81.78,63.87 U11.R8 U11.T8 ; U11.V7 83.45,63.25 v1(83.26,63.44) 83.72,63.9 U11.V8 ; U11.N8 U11.N7 80.79,62.95 v1(80.92,62.95) ; U11.M8 U11.M7 79.53,63.25 v1(79.36,63.42) ; U11.K8 U11.K7 78.64,63.25 v1(78.96,62.93)
  TOP w0.762: v3(130.81,99.63) 130.81,99.62 v3(129.74,98.55) 130.18,98.12 130.18,89.05 v3(129.41,88.29)
  L3_SIG1 w0.762: 61.98,38.48 61.98,36.97 61.9,36.89 61.9,35.9 63.95,33.85 63.95,31.93 64.9,30.99 64.9,30.1 63.58,28.78 63.58,24.31 68.78,19.1 76.9,19.1 77,19 78.12,19 78.69,18.43 79.75,17.37 83.41,17.37 84.33,18.29 87.88,18.29 89.03,17.14 90.65,17.14 91.52,18.01 ; 99.11,22.35 104.01,27.25 104.01,38.57 108.62,43.18 112.37,43.18 120.17,50.98 121.59,50.98 122.55,51.94 125.91,51.94 128.72,54.76 128.72,59.89 132.59,63.75 132.59,68.58 133.05,69.04 133.05,70.02 129.41,73.66 v3(129.41,88.29)
  BOTTOM w0.381: C234.1 78.44,64.35 v1(79.36,63.42) 79.42,63.47 C236.1 ; C240.1 83.82,62.74 83.26,63.3 v1(83.26,63.44) 83.19,63.52 C231.1 ; v1(78.96,62.93) 78.52,62.48 C241.1 ; C233.1 81.03,63.71 v1(81.33,63.41)
  BOTTOM w0.508: v3(130.81,99.63) R313.2 v3(129.74,98.55)
  vias: v3(128.4,88.27) v4(51.69,47.24) v4(51.69,45.59) v4(51.69,43.94) v4(53.34,47.24) v4(53.34,45.59) v4(53.34,43.94)
V1_5DREG: length 5
  BOTTOM w0.203: 39.75,46.99 U52.B2 U52.A2 39.62,47.49
V1_8D: length 291.3
  TOP w0.508: v3(28.58,101.73) 29.58,102.73 43.16,102.73 v3(45.92,105.49) ; v3(124.21,117.6) 123.95,117.6 R1.2 123.33,116.95 Q1.G ; R229.2 v3(56.9,12.83)
  L3_SIG1 w0.508: v3(45.92,105.49) 47.14,106.71 47.14,113.11 49.63,115.6 52.53,115.6 57.26,110.86 63.93,110.86 65.91,112.84 104.71,112.84 v3(106.3,111.25) 107.7,112.65 119.89,112.65 120.4,113.16 120.4,117.86 120.78,118.24 123.57,118.24 v3(124.21,117.6)
  L3_SIG1 w0.635: 105.97,27.13 105.97,25.63 100.53,20.19
  L3_SIG1 w0.762: 105.97,27.13 105.16,27.94 105.16,38.1 108.84,41.78 112.59,41.78 120.64,49.83 127.81,49.83 129.29,51.31 129.29,52.32 131.14,54.18 131.14,58.52 133.34,60.72 133.34,61.46 134.86,62.98 134.86,71.11 134.09,71.88 133.73,71.88 130.62,74.99 130.62,88.71 129.74,89.59 127.64,89.59 124.76,86.72 122.3,86.72 117.53,81.94 114.53,81.94 113.28,83.19 v4(110.36,83.19) ; v3(56.9,12.83) 57.23,12.83 59.31,14.91 61.39,14.91 61.77,15.29 65.54,15.29 68.21,17.96 76.42,17.96 76.53,17.86 77.65,17.86 79.34,16.17 83.78,16.17 85.19,14.76 90.91,14.76 92.43,16.28 93.38,16.28 95.26,18.16 96.35,18.16 97.23,19.04 97.23,19.67 97.75,20.19 100.53,20.19
  BOTTOM w0.381: U33.3 28.43,100.98 C139.1
  BOTTOM w0.508: R479.2 v3(108.08,51.82) ; v3(105.16,101.22) 108.33,101.22 108.71,101.6 R309.2 ; C139.1 v3(28.58,101.73)
  vias: v3(99.31,100.46) v3(99.26,99.42) v3(106.93,59.74) v4(108.58,83.19) v4(108.84,85.34) v4(110.11,85.34)
V1_8D_AM437X: length 13.4
  TOP w0.254: v1(73.76,73.23) 73.76,73.42 U11.C23
  TOP w0.508: v3(106.53,61.59) R142.2 v3(107.57,62.58) ; R149.2 v3(103.76,59.94) ; v3(100.03,66.12) 99.85,66.29 98.98,66.29 98.74,66.05 FB6.2 99.22,65.18 v3(99.92,65.18)
  BOTTOM w0.508: C192.1 73.66,73.33 v1(73.76,73.23) ; v3(99.92,65.18) 99.22,65.18 FB6.2 98.74,66.04 98.99,66.29 99.85,66.29 v3(100.03,66.12) ; v3(69.21,86.2) 69.18,86.17 FB9.1 v3(67.95,87.3)
  vias: v3(69.55,83.19) v3(78.61,89.41) v3(81.28,89.53) v3(86.61,93.09) v3(87.88,93.09) v3(89.15,93.09) v3(96.14,97.03) v3(96.57,97.99) v3(102.29,68.3)
V1_8DADC: length 75.2
  TOP w0.508: R110.1 100.58,68.83 v3(100.33,68.58) 100.08,68.33 R126.1
  L3_SIG1 w0.508: v3(109.37,96.09) 110.82,96.09 116.59,101.85 v3(118.86,101.85)
  BOTTOM w0.508: v3(109.37,96.09) 109.37,91.83 108.53,90.99 108.53,89.99 108.31,89.76 108.31,88.04 106.48,86.21 106.48,82.64 108.99,80.13 108.99,79.3 109.45,78.84 109.45,77.01 107.31,74.88 105.92,74.88 105.59,74.55 105.59,74.01 104.27,72.69 100.58,72.69 100.03,72.14 100.03,68.88 v3(100.33,68.58) ; 131.83,116.46 131.83,115.65 132.08,115.39 132.08,112.77 128.79,109.47 122.81,109.47 121.98,108.65 120.59,108.65 120.13,108.19 120.13,106.32 119.84,106.03 119.84,104.97 118.86,103.99 v3(118.86,101.85)
V1_8DEN: length 229.8
  TOP w0.13: U26.15 64.34,9.7 64.64,9.4 65.23,9.4 v1(65.74,9.91) R237.1
  L3_SIG1 w0.13: v1(138.43,73.53) 136.58,75.38 136.58,84.63 135.13,86.08 135.13,87.38 v1(134.87,87.63) ; v1(65.74,9.91) 65.74,10.01 67.35,11.62 74.05,11.62 74.91,10.76 75.69,10.76 76.14,10.31 77.13,9.32 77.51,8.94 90.72,8.94 91.38,8.28 95.79,8.28 96.43,8.93 100.16,8.93 100.5,9.26 102.86,9.26 104.72,11.12 104.72,14.13 108.43,17.84 108.43,20.79 110.64,23 110.64,24.9 114.86,29.12 118.59,29.12 118.98,29.51 118.98,32.96 120.18,34.15 120.18,34.96 120.85,35.64 131.9,35.64 136.89,40.62 136.89,50.27 137.21,50.6 137.21,50.6 v1(137.92,51.31)
  L4_SIG2 w0.13: v1(138.43,73.53) 137.16,73.53 135.81,72.19 135.81,70.54 136.78,69.57 136.78,59.05 137.52,58.32 137.52,51.71 v1(137.92,51.31)
  BOTTOM w0.13: R490.2 41.27,42.16 42.8,40.64 47.62,40.64 50.55,37.72 51.43,37.72 54.8,34.36 54.8,24.8 53.72,23.72 53.72,21.34 55.53,19.52 55.53,14.79 54.1,13.36 54.1,11 57.05,8.06 60.38,8.06 62.92,10.59 65.05,10.59 v1(65.74,9.91) ; v1(134.87,87.63) 131.08,87.63 130.43,88.28 130.43,88.9 129.79,89.53 127.76,89.53 126.75,88.52 122.93,88.52 120.78,90.67 117.92,90.67 117.46,90.21 117.46,88.51 R359.2
V1_8DREG: length 8.2
  BOTTOM w0.203: 119.71,83.7 119.21,84.2 U40.B2 U40.A2 119.71,83.7 ; 119.71,83.7 C175.1
V1_8FTDI: length 14.5
  TOP w0.254: U13.49 113.48,54.04 113.16,53.72 C76.1 ; C61.1 125.48,63.63 124.75,62.9 123.84,62.9 123.65,62.71 U13.12 ; C73.1 121.54,53.22 120.98,53.78 U13.64
  TOP w0.305: U13.37 v3(109.73,62.71)
  TOP w0.508: C61.1 v3(126.24,62.81) ; C76.1 v3(112.27,52.83) ; C73.1 v3(122.05,53.98)
  BOTTOM w0.508: v3(109.73,62.71) 110.26,62.71 110.29,62.74 C239.1
  vias: v3(109.86,57.4) v3(109.86,56.13)
V2_5MTR: length 37.8
  TOP w0.508: v3(27.56,35.56) 27.05,35.56 26.8,35.31 R194.2 ; 51.31,28.83 v3(51.31,28.07) ; R196.2 v1(58.93,34.54) ; R210.2 v3(57.78,30.1)
  L3_SIG1 w0.508: v3(52.9,38.86) 51.56,38.86 43.69,46.74 41.79,46.74 38.18,43.12 37.05,43.12 32.79,38.86 30.86,38.86 v3(27.56,35.56)
  BOTTOM w0.508: U56.2 v3(52.9,38.86)
V2_8A: length 1.9
  TOP w0.203: J5.3 124.4,106.23 124.39,106.23
  TOP w0.381: C15.1 124.39,106.23
V2_8D: length 16.8
  TOP w0.203: 120.8,105.7 J5.12
  TOP w0.381: 120.8,105.7 120.8,106.06 119.99,106.87 C13.1
  TOP w0.508: C13.1 v3(118.81,106.87) ; C25.1 v3(117.73,94.36) ; R16.2 v3(131.12,107.88) ; v3(123.25,108.65) R15.2
  BOTTOM w0.305: C140.1 133.72,99.05 U31.3
  BOTTOM w0.381: U34.6 126.63,96.41 C146.1 ; C145.1 135.63,97.14 U38.16
  BOTTOM w0.508: v3(122.43,111.59) C123.1 v3(124.84,111.59) ; C145.1 v3(134.89,97.16) ; R305.2 120.78,103.38 v3(120.43,103.03) ; C146.1 v3(127.64,96.65) ; C140.1 v3(133.66,98.17)
  vias: v3(117.86,106.81) v3(117.86,105.54) v3(130.43,108.97) v3(131.06,109.86)
V2_8D_EN: length 4.6
  BOTTOM w0.13: R309.1 110.11,102.62 110.11,104.9 109.48,105.53 U30.3
V2_8D_FB: length 3.8
  BOTTOM w0.508: R306.1 C135.2 ; R306.1 U30.5 ; R306.1 R301.2
V3_3D: length 264.8
  TOP w0.254: U25.10 94.85,11.45 R233.2
  TOP w0.305: C64.1 27.81,61.47 U12.21 ; U7.21 27.81,86.75 C37.1 ; U27.10 v3(47.37,6.48)
  TOP w0.381: U8.5 118.22,83.17 C41.1 ; U6.1 116.45,100.06 C20.1 ; U9.20 v3(58.55,79.37) ; R233.2 95,11.07 94.62,10.69 92.18,10.69 91.82,11.05 R232.2 ; C37.1 v3(28.56,86.74) ; R69.2 v3(76.33,88.39) ; U1.1 v3(9,117.16) ; U2.1 v3(17.05,117.16) ; v3(28.56,61.47) C64.1 ; v3(77.29,84.86) 77.09,84.66 R87.2
  TOP w0.508: R40.2 v3(63.88,97.16) ; R236.2 v3(48.26,10.16) ; v3(25.78,48.39) 25.27,47.88 v3(25.27,42.71) ; v3(32.89,43.81) 27.43,43.81 26.33,42.71 v3(25.27,42.71) ; v3(56.9,4.45) 57.15,4.19 C115.1 ; C20.1 v3(117.22,100.08) ; v3(25.27,42.71) v3(24,42.71) ; R267.2 v3(44.45,6.73) ; v3(23.37,85.34) 23.75,85.72 24.26,85.72 ; R50.1 v3(19.69,94.23) ; R38.2 v3(61.09,97.16) ; R26.2 R25.2 v3(60.71,100.97) ; C41.1 v3(117.35,83.06) ; R56.1 v3(19.69,91.06) ; v3(56.9,10.41) 57.02,10.54 R235.1 ; R42.2 v3(66.93,97.16) ; R125.1 v3(19.69,68.96) ; v3(63.5,100.97) R27.2 R28.2 ; C63.1 39.32,62.1 v3(39.37,62.15) ; R266.2 v3(43.31,6.73) ; R39.2 v3(62.48,97.16) ; R145.2 v3(23.31,60.45) ; C115.1 v3(57.95,5.33) ; C115.1 57.91,4.15 C116.1 57.78,2.67 56.77,2.67 v3(56.77,2.66) ; R31.1 20.07,98.3 v3(19.43,97.66) ; v3(28.83,19.3) 28.83,20.7 29.91,21.78 29.91,23.91 29.13,24.69 19.63,24.69 v3(16.13,28.19) 6.6,28.19 v3(4.19,30.61) ; v3(66.29,100.97) R29.2 R30.2 ; R47.2 68.71,95.48 v3(68.55,95.63) ; R244.2 v3(48.26,9.02) ; R37.2 v3(59.69,97.16) ; R54.2 74.04,91.95 73.53,91.44 v3(73.41,91.44) ; R131.1 v3(19.56,65.79) ; R106.1 v3(19.69,69.98) ; v3(102.29,74.37) 102.29,74.04 101.02,72.77 R100.2 ; R49.2 v3(71.88,95.63) ; R48.2 v3(70.48,95.63) ; R35.2 v3(56.9,97.16) ; R36.2 v3(58.29,97.16) ; R43.1 v3(19.69,95.25) ; v3(57.91,100.97) R23.2 R24.2 ; R101.1 v3(19.69,73.02) ; J7.5 v3(137.67,76.96) ; R75.2 v3(85.72,88.01) ; C34.1 v3(64.26,86.87) ; R41.2 v3(65.53,97.16) ; R96.2 v3(101.47,76.2) ; R231.2 v3(48.26,11.43)
  L3_SIG1 w0.762: v3(110.49,19.94) v3(110.49,18.8) 111.63,17.65 117.98,17.65 127.35,8.29 J16.1
  L4_SIG2 w0.508: v3(134.11,58.03) 132.96,58.03 132.08,57.15 132.08,55.14 132.97,54.25 v1(132.97,52.7) 132.97,50.93 v1(133.93,49.97) 133.35,49.38 133.35,48.91 v3(128.78,44.34) ; v3(129.79,71.5) 129.79,75.82 v3(128.4,77.22) 129.41,77.22 130.94,78.74 130.94,80.64 v3(132.33,82.04)
  BOTTOM w0.203: U49.3 v1(133.93,49.97)
  BOTTOM w0.254: 101.06,94.33 101.2,94.19 U35.A4 ; 103.5,94.11 102.87,94.11 U35.A1 ; 103.25,91.31 102.7,91.87 U35.D1
  BOTTOM w0.305: C126.1 134.37,105.8 U31.7 ; U59.1 v3(51.82,18.17)
  BOTTOM w0.381: U44.5 16.14,78.09 C185.1 v3(16.89,78.11) ; U58.1 30.84,28.68 31.12,28.96 C319.1 ; U46.2 39.32,62.1 v3(39.37,62.15) ; v3(24.38,93.73) 24.66,93.45 R346.1 25.4,94.4 v3(25.18,94.61) ; U50.5 123.17,46.89 C274.2 ; U39.20 64.26,86.86 v3(64.26,86.87) ; R402.2 v3(137.67,82.04) ; C166.1 135.63,87.77 U38.1 ; U34.1 126.63,91.93 C156.1 ; C178.1 22.86,82.64 22.87,82.63 U43.5 ; R455.2 v3(34.7,64.48) ; v3(106.05,53.59) C263.1 106.81,55.36 U48.5 ; J19.4 v3(56.77,2.66) ; U32.8 C127.1 ; v3(125.47,45.85) 125.47,45.85 125.84,45.85 125.84,45.85 C275.2 126.36,45.98 126.36,46.86 126.35,46.87 U51.5
  BOTTOM w0.508: v3(18.41,83.4) 18.43,83.38 19.37,83.38 R380.2 v3(19.43,82.3) ; C274.2 v3(124.71,46.1) ; v3(30.35,29.46) C319.1 ; R542.2 28.45,19.69 v3(28.83,19.3) ; C126.1 v3(135.45,106.11) ; R343.2 v3(115.95,95.38) ; v3(25.78,48.39) C267.1 U55.8 ; R412.2 v3(24.26,81.14) ; v3(102.49,87.33) 102.49,87.38 103,87.88 R355.2 ; 3.3,30.1 3.81,30.61 v3(4.19,30.61) ; 3.3,30.1 3.43,30.1 4.06,29.46 U57.8 ; 3.3,30.1 C320.1 ; R495.1 v3(37.85,38.99) ; R101.1 v3(19.69,73.02) ; v3(32.89,43.81) 34.92,43.81 36.65,42.09 Q10.S v3(36.65,40.54) ; v3(58.55,79.37) 57.66,79.37 C183.1 ; R297.2 v3(133.54,107.88) ; v3(24.38,68.45) 24.66,68.18 R446.1 25.4,69.13 v3(25.18,69.34) ; R403.2 v3(132.33,82.04) ; R125.1 v3(19.69,68.96) ; R424.2 v3(103.63,77.6) ; v3(135.76,87) 135.64,87.12 C166.1 ; v3(137.67,76.96) C190.1 ; C156.1 v3(127.64,91.69) ; R420.2 v3(5.33,78.99) ; R458.2 v3(60.71,63.37) ; C147.1 19.69,95.5 v3(19.69,95.25) ; R548.2 51.84,16.89 v3(51.83,16.88) ; R472.2 v3(134.11,58.03) ; R50.1 v3(19.69,94.23) ; v3(28.56,61.47) 27.94,62.09 R462.2 ; U55.3 v3(24,42.71) ; R310.2 v3(3.3,103) ; C127.1 v3(87.12,106.68) ; 15.11,28.19 v3(16.13,28.19) ; R456.2 v3(68.61,64.39) ; v3(128.4,77.22) R426.2 ; C178.1 v3(23.61,82.8) ; R411.2 v3(2.79,79.34) ; v3(126.62,86.23) 127.25,86.23 128.02,87 129.67,87 130.18,86.49 C169.1 ; R347.2 v3(127.89,92.46) ; R438.2 v3(21.46,70.48) ; R300.2 v3(84.07,105.92) ; R418.2 v3(102.87,79.5) ; v3(33.53,80.14) R401.2 v3(32.38,81.4) ; U55.2 v3(25.27,42.71) ; R475.2 v3(3.43,55.37)
  vias: v3(28.32,97.79) v3(42.29,74.68) v3(42.29,72.14) v3(43.56,73.41) v3(43.56,72.14) v3(49.76,54.1) v3(51.05,54.1) v3(57.4,16.38) v3(58.67,18.92) v3(58.67,17.65) v3(58.67,16.38) v3(59.94,18.92) v3(59.94,17.65) v3(59.94,16.38) v3(92.66,105.89) v3(94.59,105.89) v3(99.69,14.73) v3(99.69,12.95) v3(105.92,103.89) v3(105.92,102.62) v3(107.19,102.62) v3(118.11,91.31) v3(118.11,90.04) v3(118.11,88.77) v3(118.11,87.5) v3(119.13,45.01) v3(119.13,44.07) v3(119.38,91.31) v3(119.38,90.04) v3(119.38,88.77) v3(119.38,87.5) v3(120.65,64.52) v3(122.17,67.44) v3(123.32,66.29) v4(68.07,102.49) v4(69.85,106.05) v4(69.85,104.27) v4(69.85,102.49) v4(100.46,101.22) v4(100.46,99.45) v4(102.23,101.22) v4(102.23,99.44) v4(107.7,95.89) v4(107.7,94.23)
V3_3D_AM437X: length 18.6
  TOP w0.203: U11.G13 U11.G14 ; U11.W16 U11.V16
  TOP w0.254: U11.G14 76.59,68.12 v1(76.77,68.31) ; v1(76.26,68.64) 75.94,68.96 U11.F16 ; U11.H11 U11.G11 v1(76.59,66.32) ; U11.W18 84.38,70.67 v1(84.21,70.85) ; v1(76.79,64.38) 76.79,64.55 76.81,64.57 76.81,64.72 77.24,65.15 U11.H10 U11.G10 ; U11.F22 75.63,73 v1(75.45,73.18) ; U11.G16 U11.G17 ; U11.G17 U11.H17 ; U11.G17 76.59,69.87 v1(76.28,70.17) ; v1(83.57,71.79) 83.17,71.79 U11.U20 ; v1(78.06,70.89) 77.89,70.72 U11.J18 U11.K18 U11.K17 ; v1(84.24,69.92) 83.9,69.92 U11.V17 U11.V16 ; U11.P18 U11.N18 U11.N19 80.16,71.05 v1(80.02,70.91) ; U11.H9 77.34,64.44 77.34,64.01 U11.H8 77.24,63.81 v1(76.89,63.46) ; U11.W20 84.84,72.15 v1(85.2,72.15) ; U11.J8 U11.J7 v1(77.41,63.25)
  BOTTOM w0.381: C193.1 84.96,72.39 v1(85.2,72.15) ; C195.1 83.13,72.23 v1(83.57,71.79)
  vias: v3(53.59,53.85) v3(53.85,69.72) v3(53.85,63.63) v3(53.98,76.33) v3(54.48,55.88) v3(54.48,54.36) v3(54.61,70.99) v3(54.61,64.9) v3(54.74,77.6)
V3_3D_PRUETH0JCK: length 8.1
  BOTTOM w0.508: J6.3 13.97,93.77 ; J6.3 12.54,92.34 ; J6.3 13.97,92.34 ; J6.3 12.54,93.77 ; J6.4 16.51,92.5 ; J6.4 15.08,91.07 ; J6.4 15.08,92.5 ; J6.4 16.51,91.07
V3_3D_PRUETH1JCK: length 8.1
  BOTTOM w0.508: 15.08,67.07 J9.4 ; J9.4 16.51,68.5 ; J9.4 16.51,67.07 ; J9.4 15.08,68.5 ; 12.54,68.34 J9.3 ; J9.3 12.54,69.77 ; J9.3 13.97,69.77 ; J9.3 13.97,68.34
V3_3DREG: length 286
  TOP w0.254: U26.14 63.84,9.23 C114.1
  TOP w0.508: C114.1 v3(62.48,8.64) ; R224.2 65.66,18.54 v3(65.66,18.8) ; R237.2 69.55,9.91 v3(69.57,9.88) ; v3(68.71,14.1) R228.2 ; R234.2 v3(69.47,11.05)
  L3_SIG1 w0.508: v3(17.32,50.9) 17.33,50.89 20.1,50.89 21.72,49.28 21.72,46.02 22.53,45.21 22.53,32.72 23.62,31.63 23.62,25.15 24.13,24.64 27.18,24.64 28.3,25.76 32.72,25.76 37.08,21.39 37.08,19.05 42.51,13.63 51.48,13.63 54.02,11.08 54.02,10.45 56.67,7.8 61.65,7.8 v3(62.48,8.64) ; v3(56.21,106.27) 56.24,106.27 v3(56.9,106.93) ; v3(106.3,29.08) 106.3,36.96 108.33,38.99 110.87,38.99 112.39,40.51 123.98,40.51 125.38,39.12 127.51,39.12 v3(129.41,41.02)
  L4_SIG2 w0.508: v3(14.53,50.89) 14.53,53.73 17.17,56.37 17.17,58.6 17.65,59.09 17.65,70.64 16.26,72.03 15.71,72.03 13.21,74.53 13.21,83.82 11.56,85.47 11.56,98.04 13.72,100.2 13.72,101.85 16.51,104.65 16.51,105.54 18.39,107.41 25.92,107.41 27.95,105.38 43.87,105.38 44.91,104.34 54.28,104.34 v3(56.21,106.27)
  BOTTOM w0.381: U54.5 133.84,40.91
  BOTTOM w0.508: v3(65.66,18.8) 66.83,18.8 69.07,16.56 70.79,16.56 73.66,13.69 87.35,13.69 88.37,14.71 90.58,14.71 92.46,12.83 97.79,12.83 98.68,13.72 99.76,13.72 101.14,15.1 101.14,16.98 106.81,22.65 106.81,28.58 v3(106.3,29.08) ; v3(129.41,41.02) 133.73,41.02 C281.1
  vias: v3(15.37,50.9) v3(16.28,50.9) v3(56.11,107.21) v3(56.79,107.87)
V3_3FTDI: length 36.3
  TOP w0.254: v3(116.83,56.63) 116.98,56.49 U13.56 ; U13.31 113.98,68.02 113.41,68.58 v3(113.41,69.09) ; U13.20 v3(119.48,68.2) ; U13.42 v3(112.78,60.21) ; v3(113.82,56.75) 113.98,56.59 U13.50
  TOP w0.508: R178.2 v3(121.79,48.39) ; R135.2 v3(128.01,64.77)
  BOTTOM w0.203: C170.1 132.04,84.55 U41.1
  BOTTOM w0.508: v3(121.79,48.39) 121.79,51.41 122.83,52.45 122.83,54.33 v3(122.05,55.12) ; C170.1 133.86,85.22 134.22,85.58 137.31,85.58 138.48,84.41 138.48,75.23 v3(138.05,74.8) ; C235.1 v3(129.67,64.64)
  vias: v3(128.4,68.58) v3(131.57,52.7)
V3_3MTR: length 29.7
  TOP w0.508: R190.2 48.4,38.98 v3(48.13,39.24) ; R223.2 v3(60.83,21.08) ; R204.2 v3(60.83,30.35) ; v3(40.89,39.37) 39.88,40.39 37.58,40.39 36.97,39.78 36.47,39.78 33.4,36.7 33.4,30.86 31.24,28.7 29.46,28.7 28.32,29.84 R201.2 ; v3(52.2,24.64) R214.2
  BOTTOM w0.508: R500.2 v3(54.36,36.2) ; R505.2 v3(49.4,36.96) ; v3(40.89,39.37) R496.1
V3_3MTRB: length 3.6
  TOP w0.254: C87.1 46.64,36.41 U23.15
  TOP w0.508: C87.1 46.61,38.09 R190.1
V5_0D: length 134.2
  TOP w0.508: v4(11.3,53.09) 11.56,52.83 R164.2 ; C110.1 v3(17.78,14.35)
  L4_SIG2 w0.508: J1.27 103.46,113.52 ; J1.27 102.03,113.52 ; J1.27 103.46,114.95 ; J1.27 102.03,114.95 ; 102.03,117.49 J1.28 ; J1.28 103.46,117.49 ; J1.28 102.03,116.06 ; J1.28 103.46,116.06 ; 14.48,16.13 J15.1 ; J15.1 16,16.13 ; J15.1 16,14.61 ; J15.1 14.48,14.61
  BOTTOM w0.381: U58.23 31.49,22.98 31.5,22.99
  BOTTOM w0.508: 31.5,22.99 31.5,23.11 30.86,23.75 C336.1 v3(28.7,23.75) ; J1.28 103.46,116.06 ; J1.28 102.03,116.06 ; J1.28 103.46,117.49 ; J1.28 102.03,117.49 ; R552.2 v3(16.89,11.81) ; v3(2.41,47.12) 3.24,47.12 FB17.1 3.24,46.23 v3(2.41,46.23) ; 102.03,113.52 J1.27 ; J1.27 103.46,114.95 ; J1.27 102.03,114.95 ; J1.27 103.46,113.52 ; 35.69,17.14 v3(35.69,16.38) ; 17.65,6.73 v3(17.65,5.97) ; 37.72,17.14 v3(37.72,16.38) ; 34.67,17.14 v3(34.67,16.38) ; v3(35.43,8.38) 37.21,6.6 40,6.6 41.15,7.75 47.25,7.75 48.85,6.15 62.76,6.15 64.52,4.39 66.82,4.39 69.28,1.93 125.42,1.93 127.32,3.84 J16.2 ; 36.7,17.14 v3(36.7,16.38) ; R560.2 v3(16.89,9.27)
  vias: v3(126.49,117.86) v3(127.38,117.86) v4(9.53,54.86) v4(9.53,53.09) v4(11.3,54.86)
V5_0DENCOD: length 2.1
  BOTTOM w0.508: R483.1 5.66,48.57 FB17.2
V5_0VOP: length 5.6
  TOP w0.305: v3(80.37,104.47) 80.36,104.46 U4.15 79.79,106.14 C16.1
  TOP w0.508: v3(73.41,94.36) 73.53,94.24 C24.1
  BOTTOM w0.381: U36.5 v3(73.41,94.36)
  BOTTOM w0.508: C138.1 81.03,103.81 v3(80.37,104.47)
V24_0D: length 64.4
  L3_SIG1 w0.762: v3(77.77,94.07) 77.77,94.66 81.66,98.55 81.66,103.07 83.13,104.55 83.13,106.62 84.34,107.82 84.34,107.84 86.23,109.73 v3(86.23,111.11)
  L5_PWR w0.508: 84.25,117.49 J1.14 ; J1.14 85.68,117.49 ; J1.14 85.68,116.06 ; J1.14 84.25,116.06 ; 81.71,116.06 J1.12 ; J1.12 83.14,117.49 ; J1.12 81.71,117.49 ; J1.12 83.14,116.06 ; J1.10 80.6,117.49 ; J1.10 80.6,116.06 ; J1.10 79.17,116.06 ; J1.10 79.17,117.49 ; 69.01,117.49 J1.2 ; J1.2 70.44,116.06 ; J1.2 70.44,117.49 ; J1.2 69.01,116.06 ; J1.8 78.06,116.06 ; J1.8 78.06,117.49 ; J1.8 76.63,116.06 ; J1.8 76.63,117.49 ; J1.16 88.22,117.49 ; J1.16 86.79,116.06 ; J1.16 88.22,116.06 ; J1.16 86.79,117.49 ; J1.6 75.52,116.06 ; J1.6 74.09,117.49 ; J1.6 74.09,116.06 ; J1.6 75.52,117.49 ; J11.1 26.08,29.63 ; J11.1 26.08,28.02 ; J11.1 24.47,28.02 ; J11.1 24.47,29.63 ; J1.4 72.98,116.06 ; J1.4 71.55,117.49 ; J1.4 72.98,117.49 ; J1.4 71.55,116.06 ; 122.38,33.48 TP14.1 ; TP14.1 122.38,35.1 ; TP14.1 124,35.1 ; TP14.1 124,33.48
  BOTTOM w0.508: R338.2 v3(77.77,94.07) 77.72,94.02 C154.1
  vias: v4(32.26,56.9) v4(32.26,55.24) v4(34.04,58.55) v4(34.04,56.9) v4(34.04,55.24) v4(35.69,58.55) v4(35.69,56.9) v4(35.69,55.24) v4(50.29,114.55) v4(50.29,112.9) v4(50.29,111.25) v4(51.94,114.55) v4(51.94,112.9) v4(51.94,111.25) v4(112.9,23.75) v4(112.9,22.1) v4(112.9,20.45) v4(112.9,18.8) v4(114.17,23.75) v4(114.17,22.1) v4(114.17,20.45) v4(114.17,18.8) v4(117.35,23.62) v4(118.62,23.62) v4(119.89,38.61) v4(119.89,36.96) v4(119.89,26.16) v4(119.89,24.51) v4(121.16,26.16) v4(121.16,24.51) v4(121.16,22.86) v4(121.16,21.21) v4(121.16,19.56) v4(121.54,38.61) v4(121.54,36.96) v4(122.17,75.95) v4(122.17,74.3) v4(123.19,38.61) v4(123.19,36.96) v4(123.83,75.95) v4(123.83,74.3) v4(125.48,75.95) v4(125.48,74.3)
V24_0MTR: length 194.1
  TOP w0.305: v3(39.52,27.38) 40.14,28 U23.4 ; U23.11 44.69,28.23 v1(45.24,27.69)
  TOP w0.508: v3(100.86,8.38) 102.34,8.38 103.76,9.8 103.76,11.89 102.92,12.73 102.92,13.59 104.2,14.87 104.2,18.73 106.98,21.51 106.98,25.91 105,27.89 105,42.9 103.5,44.4 103.5,49.78 105.23,51.51 105.23,55.8 R154.2 ; C99.1 v3(34.67,25.91)
  L4_SIG2 w0.508: TP15.1 22.14,25.48 ; TP15.1 22.14,27.09 ; TP15.1 20.53,25.48 ; TP15.1 20.53,27.09 ; J11.2 26.08,27.09 ; J11.2 26.08,25.48 ; J11.2 24.47,27.09 ; J11.2 24.47,25.48 ; v3(65.15,5.64) 64.55,5.04 60.41,5.04 58.8,3.43 51.05,3.43 50.93,3.3 48.56,3.3 47.75,4.11 41.3,4.11 39.52,5.89 v3(39.52,27.38) ; v3(17.02,21.97) 17.02,42.16 v3(20.57,45.72)
  BOTTOM w0.508: v3(39.52,27.38) 39.52,27.71 C327.1 ; R485.1 14.21,48.27 16.76,45.72 v3(20.57,45.72) ; v3(65.15,5.64) 66.22,5.64 68.02,7.44 74.5,7.44 75.49,8.43 91.64,8.43 92.41,7.67 97.46,7.67 98.17,8.38 v3(100.86,8.38) ; C326.1 44.83,28.45 45.24,28.04 v1(45.24,27.69)
  vias: v1(35.81,31.5) v1(35.81,30.23) v3(17.02,20.7) v3(17.02,19.43) v3(17.02,18.16) v3(18.29,21.97) v3(19.56,21.97) v3(20.83,21.97)
